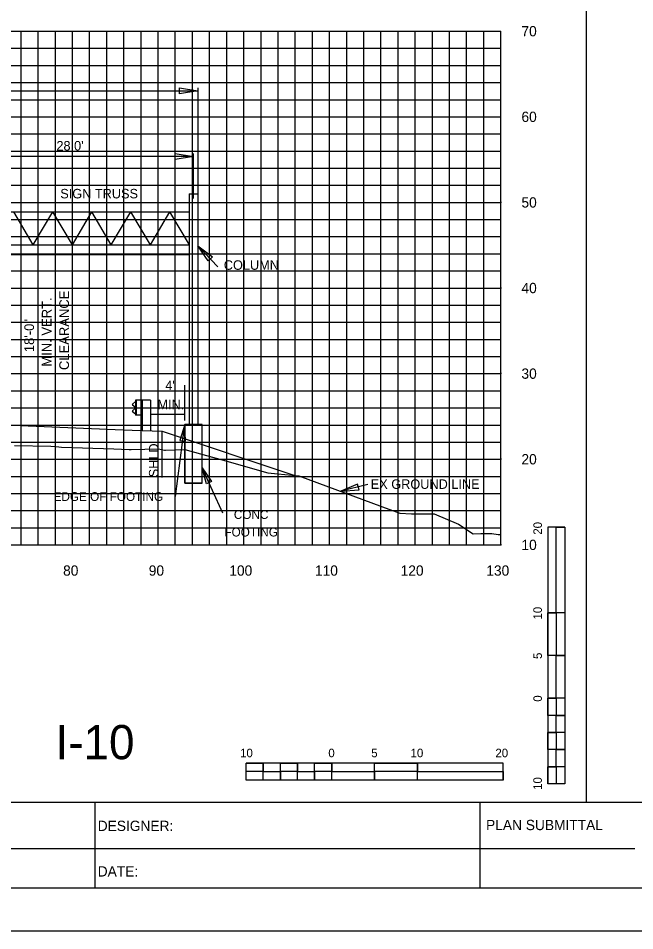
# Model space of a CAD drawing. Extents: x 2193008 to 2198143, y 1236112 to 1237864.
# Drawn here: x 2195658.4 to 2195730.3, y 1237118 to 1237224.6 of the extents above; entities that cross this region are included whole.
import ezdxf

# ---------------------------------------------------------------- set-up
doc = ezdxf.new("R2010")
doc.units = 0
for name, color, linetype in [('3', 7, 'Continuous'), ('31', 7, 'Continuous'), ('60', 7, 'Continuous'), ('ANNO-TXT', 7, 'Continuous'), ('Default', 7, 'Continuous'), ('GSDIMS', 7, 'Continuous'), ('Level 1', 7, 'Continuous'), ('Level 33', 7, 'Continuous'), ('Level 55', 7, 'Continuous'), ('Level 61', 7, 'Continuous'), ('LIMT-CSLINE', 7, 'Continuous'), ('M-ROADS', 7, 'Continuous'), ('SHT-BNDRY', 7, 'Continuous'), ('V7Level1', 7, 'Continuous')]:
    doc.layers.add(name, color=color, linetype=linetype)

msp = doc.modelspace()

# ---------------------------------------------------------------- linework, layer by layer
msp.add_lwpolyline([(2195574.71, 1237133.05), (2195874.71, 1237133.05), (2195874.71, 1237323.05), (2195574.71, 1237323.05)], close=True)
at = {"layer": '3'}
for p, q in [((2195724.71, 1237133.05), (2195724.71, 1237228.05)), ((2195724.71, 1237133.05), (2195724.71, 1237228.05)), ((2195679.32, 1237216.5), (2195679.32, 1237204.12)), ((2195584.25, 1237216.15), (2195679.32, 1237216.15)), ((2195678.32, 1237204.12), (2195678.32, 1237177.18)), ((2195679.32, 1237204.12), (2195679.32, 1237177.18)), ((2195681.69, 1237195.6), (2195679.32, 1237198.04)), ((2195677.82, 1237177.62), (2195677.82, 1237181.77)), ((2195676.73, 1237168.75), (2195677.82, 1237177.18)), ((2195679.84, 1237177.18), (2195677.82, 1237177.18)), ((2195677.82, 1237170.32), (2195677.82, 1237177.18)), ((2195679.84, 1237170.32), (2195679.84, 1237177.18)), ((2195682.27, 1237166.81), (2195679.84, 1237172.11)), ((2195679.84, 1237170.32), (2195677.82, 1237170.32)), ((2195699.19, 1237170.15), (2195696.04, 1237169.37))]:
    msp.add_line(p, q, dxfattribs=at)
at = {"layer": '60'}
for p, q in [((2195714.71, 1237163.11), (2195714.71, 1237223.11)), ((2195714.77, 1237203.11), (2195714.71, 1237203.11)), ((2195714.77, 1237193.11), (2195714.71, 1237193.11)), ((2195714.77, 1237183.11), (2195714.71, 1237183.11)), ((2195714.77, 1237173.11), (2195714.71, 1237173.11)), ((2195584.71, 1237163.11), (2195714.71, 1237163.11)), ((2195664.71, 1237163.05), (2195664.71, 1237163.11)), ((2195674.71, 1237163.05), (2195674.71, 1237163.11)), ((2195684.71, 1237163.05), (2195684.71, 1237163.11)), ((2195694.71, 1237163.05), (2195694.71, 1237163.11)), ((2195704.71, 1237163.05), (2195704.71, 1237163.11)), ((2195714.71, 1237163.05), (2195714.71, 1237163.11)), ((2195714.77, 1237163.11), (2195714.71, 1237163.11))]:
    msp.add_line(p, q, dxfattribs=at)
msp.add_lwpolyline([(2195587.2, 1237175.36), (2195596.63, 1237175.74), (2195608.63, 1237176), (2195619.96, 1237176.25), (2195631.96, 1237176.52), (2195643.96, 1237176.78), (2195657.69, 1237177.08), (2195669.69, 1237176.6), (2195671.69, 1237176.52), (2195675.19, 1237176.38), (2195690.66, 1237171.23)], dxfattribs=at)
at = {"layer": 'Default'}
msp.add_line((2195678.82, 1237203.57), (2195678.82, 1237208.83), dxfattribs=at)
at = {"layer": 'GSDIMS'}
for p, q in [((2195678.82, 1237208.48), (2195650.7, 1237208.48)), ((2195678.32, 1237204.12), (2195679.32, 1237204.12)), ((2195650.7, 1237203.12), (2195678.32, 1237203.12)), ((2195650.7, 1237202.01), (2195678.32, 1237202.01)), ((2195657.81, 1237202.01), (2195660.09, 1237198.15)), ((2195662.37, 1237202.01), (2195660.09, 1237198.15)), ((2195662.37, 1237202.01), (2195664.65, 1237198.15)), ((2195666.93, 1237202.01), (2195664.65, 1237198.15)), ((2195666.93, 1237202.01), (2195669.2, 1237198.15)), ((2195671.48, 1237202.01), (2195669.2, 1237198.15)), ((2195671.48, 1237202.01), (2195673.76, 1237198.15)), ((2195676.04, 1237202.01), (2195673.76, 1237198.15)), ((2195676.04, 1237202.01), (2195678.32, 1237198.15)), ((2195650.7, 1237198.15), (2195678.32, 1237198.15)), ((2195650.7, 1237197.04), (2195678.32, 1237197.04)), ((2195675.19, 1237170.97), (2195675.19, 1237176.38))]:
    msp.add_line(p, q, dxfattribs=at)
for points in [[(2195679.32, 1237216.15), (2195677.19, 1237215.81), (2195677.19, 1237216.5)], [(2195678.82, 1237208.48), (2195676.69, 1237208.13), (2195676.69, 1237208.83)], [(2195679.32, 1237198.04), (2195681.04, 1237196.77), (2195680.53, 1237196.29)], [(2195677.82, 1237177.18), (2195677.25, 1237175.31), (2195677.89, 1237175.23)], [(2195679.84, 1237172.11), (2195680.93, 1237170.5), (2195680.35, 1237170.23)], [(2195696.04, 1237169.37), (2195698.17, 1237169.53), (2195697.99, 1237170.21)]]:
    msp.add_lwpolyline(points, close=True, dxfattribs=at)
at = {"layer": 'Level 1'}
for p, q in [((2195672.07, 1237179.85), (2195671.71, 1237179.55)), ((2195671.71, 1237179.48), (2195672.07, 1237179.2)), ((2195672.07, 1237179.06), (2195671.71, 1237178.76)), ((2195672.07, 1237180), (2195672.07, 1237178.25)), ((2195673.82, 1237180), (2195672.07, 1237180)), ((2195672.12, 1237180), (2195672.12, 1237178.25)), ((2195672.77, 1237180), (2195672.77, 1237178.25)), ((2195672.82, 1237180), (2195672.82, 1237176.48)), ((2195673.82, 1237180), (2195673.82, 1237176.44)), ((2195671.71, 1237178.69), (2195672.07, 1237178.4)), ((2195672.82, 1237178.25), (2195672.07, 1237178.25)), ((2195720.18, 1237165.19), (2195720.18, 1237135.19)), ((2195722.18, 1237165.19), (2195720.18, 1237165.19)), ((2195722.18, 1237165.19), (2195722.18, 1237155.19)), ((2195722.18, 1237165.19), (2195722.18, 1237135.19)), ((2195721.18, 1237155.19), (2195720.18, 1237155.19)), ((2195722.18, 1237155.19), (2195720.18, 1237155.19)), ((2195721.18, 1237155.19), (2195721.18, 1237150.19)), ((2195722.18, 1237150.19), (2195720.18, 1237150.19)), ((2195722.18, 1237150.19), (2195721.18, 1237150.19)), ((2195722.18, 1237150.19), (2195722.18, 1237145.19)), ((2195721.18, 1237145.19), (2195720.18, 1237145.19)), ((2195722.18, 1237145.19), (2195720.18, 1237145.19)), ((2195721.18, 1237145.19), (2195721.18, 1237143.19)), ((2195722.18, 1237143.19), (2195721.18, 1237143.19)), ((2195722.18, 1237143.19), (2195722.18, 1237141.19)), ((2195721.18, 1237141.19), (2195720.18, 1237141.19)), ((2195721.18, 1237141.19), (2195721.18, 1237139.19)), ((2195722.18, 1237139.19), (2195721.18, 1237139.19)), ((2195722.18, 1237139.19), (2195722.18, 1237137.19)), ((2195714.97, 1237137.63), (2195684.97, 1237137.63)), ((2195684.97, 1237135.63), (2195684.97, 1237137.63)), ((2195686.97, 1237136.63), (2195686.97, 1237137.63)), ((2195690.97, 1237136.63), (2195690.97, 1237137.63)), ((2195694.97, 1237136.63), (2195694.97, 1237137.63)), ((2195694.97, 1237135.63), (2195694.97, 1237137.63)), ((2195699.97, 1237135.63), (2195699.97, 1237137.63)), ((2195704.97, 1237136.63), (2195704.97, 1237137.63)), ((2195704.97, 1237135.63), (2195704.97, 1237137.63)), ((2195714.97, 1237135.63), (2195714.97, 1237137.63)), ((2195686.97, 1237136.63), (2195684.97, 1237136.63)), ((2195688.97, 1237135.63), (2195688.97, 1237136.63)), ((2195690.97, 1237136.63), (2195688.97, 1237136.63)), ((2195692.97, 1237135.63), (2195692.97, 1237136.63)), ((2195694.97, 1237136.63), (2195692.97, 1237136.63)), ((2195699.97, 1237135.63), (2195699.97, 1237136.63)), ((2195704.97, 1237136.63), (2195699.97, 1237136.63)), ((2195721.18, 1237137.19), (2195720.18, 1237137.19)), ((2195721.18, 1237137.19), (2195721.18, 1237135.19)), ((2195714.97, 1237135.63), (2195684.97, 1237135.63)), ((2195688.97, 1237135.63), (2195686.97, 1237135.63)), ((2195692.97, 1237135.63), (2195690.97, 1237135.63)), ((2195699.97, 1237135.63), (2195694.97, 1237135.63)), ((2195714.97, 1237135.63), (2195704.97, 1237135.63)), ((2195722.18, 1237135.19), (2195720.18, 1237135.19))]:
    msp.add_line(p, q, dxfattribs=at)
for points in [[(2195721.18, 1237155.19), (2195721.18, 1237165.19), (2195722.18, 1237165.19), (2195722.18, 1237155.19)], [(2195720.18, 1237150.19), (2195720.18, 1237155.19), (2195721.18, 1237155.19), (2195721.18, 1237150.19)], [(2195721.18, 1237145.19), (2195721.18, 1237150.19), (2195722.18, 1237150.19), (2195722.18, 1237145.19)], [(2195720.18, 1237143.19), (2195720.18, 1237145.19), (2195721.18, 1237145.19), (2195721.18, 1237143.19)], [(2195721.18, 1237141.19), (2195721.18, 1237143.19), (2195722.18, 1237143.19), (2195722.18, 1237141.19)], [(2195720.18, 1237139.19), (2195720.18, 1237141.19), (2195721.18, 1237141.19), (2195721.18, 1237139.19)], [(2195721.18, 1237137.19), (2195721.18, 1237139.19), (2195722.18, 1237139.19), (2195722.18, 1237137.19)], [(2195684.97, 1237137.63), (2195686.97, 1237137.63), (2195686.97, 1237136.63), (2195684.97, 1237136.63)], [(2195688.97, 1237137.63), (2195690.97, 1237137.63), (2195690.97, 1237136.63), (2195688.97, 1237136.63)], [(2195692.97, 1237137.63), (2195694.97, 1237137.63), (2195694.97, 1237136.63), (2195692.97, 1237136.63)], [(2195699.97, 1237137.63), (2195704.97, 1237137.63), (2195704.97, 1237136.63), (2195699.97, 1237136.63)], [(2195686.97, 1237136.63), (2195688.97, 1237136.63), (2195688.97, 1237135.63), (2195686.97, 1237135.63)], [(2195690.97, 1237136.63), (2195692.97, 1237136.63), (2195692.97, 1237135.63), (2195690.97, 1237135.63)], [(2195694.97, 1237136.63), (2195699.97, 1237136.63), (2195699.97, 1237135.63), (2195694.97, 1237135.63)], [(2195704.97, 1237136.63), (2195714.97, 1237136.63), (2195714.97, 1237135.63), (2195704.97, 1237135.63)], [(2195720.18, 1237135.19), (2195720.18, 1237137.19), (2195721.18, 1237137.19), (2195721.18, 1237135.19)]]:
    msp.add_lwpolyline(points, close=True, dxfattribs=at)
for centre in [(2195671.74, 1237179.52), (2195671.74, 1237178.72)]:
    msp.add_arc(centre, 0.05, 135, 226.6208, dxfattribs=at)
at = {"layer": 'Level 61'}
msp.add_line((2195673.82, 1237178.37), (2195677.82, 1237178.37), dxfattribs=at)
at = {"layer": 'M-ROADS'}
for p, q in [((2195584.71, 1237223.11), (2195714.71, 1237223.11)), ((2195658.71, 1237163.11), (2195658.71, 1237223.11)), ((2195660.71, 1237163.11), (2195660.71, 1237223.11)), ((2195662.71, 1237163.11), (2195662.71, 1237223.11)), ((2195664.71, 1237163.11), (2195664.71, 1237223.11)), ((2195666.71, 1237163.11), (2195666.71, 1237223.11)), ((2195668.71, 1237163.11), (2195668.71, 1237223.11)), ((2195670.71, 1237163.11), (2195670.71, 1237223.11)), ((2195672.71, 1237163.11), (2195672.71, 1237223.11)), ((2195674.71, 1237163.11), (2195674.71, 1237223.11)), ((2195676.71, 1237163.11), (2195676.71, 1237223.11)), ((2195678.71, 1237163.11), (2195678.71, 1237223.11)), ((2195680.71, 1237163.11), (2195680.71, 1237223.11)), ((2195682.71, 1237163.11), (2195682.71, 1237223.11)), ((2195684.71, 1237163.11), (2195684.71, 1237223.11)), ((2195686.71, 1237163.11), (2195686.71, 1237223.11)), ((2195688.71, 1237163.11), (2195688.71, 1237223.11)), ((2195690.71, 1237163.11), (2195690.71, 1237223.11)), ((2195692.71, 1237163.11), (2195692.71, 1237223.11)), ((2195694.71, 1237163.11), (2195694.71, 1237223.11)), ((2195696.71, 1237163.11), (2195696.71, 1237223.11)), ((2195698.71, 1237163.11), (2195698.71, 1237223.11)), ((2195700.71, 1237163.11), (2195700.71, 1237223.11)), ((2195702.71, 1237163.11), (2195702.71, 1237223.11)), ((2195704.71, 1237163.11), (2195704.71, 1237223.11)), ((2195706.71, 1237163.11), (2195706.71, 1237223.11)), ((2195708.71, 1237163.11), (2195708.71, 1237223.11)), ((2195710.71, 1237163.11), (2195710.71, 1237223.11)), ((2195712.71, 1237163.11), (2195712.71, 1237223.11)), ((2195714.71, 1237163.11), (2195714.71, 1237223.11)), ((2195584.71, 1237221.11), (2195714.71, 1237221.11)), ((2195584.71, 1237219.11), (2195714.71, 1237219.11)), ((2195584.71, 1237217.11), (2195714.71, 1237217.11)), ((2195584.71, 1237215.11), (2195714.71, 1237215.11)), ((2195584.71, 1237213.11), (2195714.71, 1237213.11)), ((2195584.71, 1237211.11), (2195714.71, 1237211.11)), ((2195584.71, 1237209.11), (2195714.71, 1237209.11)), ((2195584.71, 1237207.11), (2195714.71, 1237207.11)), ((2195584.71, 1237205.11), (2195714.71, 1237205.11)), ((2195584.71, 1237203.11), (2195714.71, 1237203.11)), ((2195584.71, 1237201.11), (2195714.71, 1237201.11)), ((2195584.71, 1237199.11), (2195714.71, 1237199.11)), ((2195584.71, 1237197.11), (2195714.71, 1237197.11)), ((2195584.71, 1237195.11), (2195714.71, 1237195.11)), ((2195584.71, 1237193.11), (2195714.71, 1237193.11)), ((2195584.71, 1237191.11), (2195714.71, 1237191.11)), ((2195584.71, 1237189.11), (2195714.71, 1237189.11)), ((2195584.71, 1237187.11), (2195714.71, 1237187.11)), ((2195584.71, 1237185.11), (2195714.71, 1237185.11)), ((2195584.71, 1237183.11), (2195714.71, 1237183.11)), ((2195584.71, 1237181.11), (2195714.71, 1237181.11)), ((2195584.71, 1237179.11), (2195714.71, 1237179.11)), ((2195584.71, 1237177.11), (2195714.71, 1237177.11)), ((2195584.71, 1237175.11), (2195714.71, 1237175.11)), ((2195584.71, 1237173.11), (2195714.71, 1237173.11)), ((2195584.71, 1237171.11), (2195714.71, 1237171.11)), ((2195584.71, 1237169.11), (2195714.71, 1237169.11)), ((2195584.71, 1237167.11), (2195714.71, 1237167.11)), ((2195584.71, 1237165.11), (2195714.71, 1237165.11)), ((2195584.71, 1237163.11), (2195714.71, 1237163.11))]:
    msp.add_line(p, q, dxfattribs=at)
msp.add_lwpolyline([(2195549.71, 1237118.04), (2195889.71, 1237118.04), (2195889.71, 1237338.04), (2195549.71, 1237338.04)], close=True, dxfattribs=at)
msp.add_lwpolyline([(2195657.92, 1237174.73), (2195662.19, 1237174.62), (2195663.13, 1237174.55), (2195663.43, 1237174.53), (2195669.52, 1237174.31), (2195671.31, 1237174.26), (2195671.57, 1237174.26), (2195674.75, 1237174.31), (2195675.43, 1237174.18), (2195675.49, 1237174.18), (2195675.57, 1237174.18), (2195677.83, 1237174.26), (2195682.17, 1237173.06), (2195687.51, 1237171.54), (2195688.69, 1237171.42), (2195691.13, 1237171.18), (2195700.88, 1237167.57), (2195702.9, 1237166.83), (2195704.29, 1237166.73), (2195705.74, 1237166.73), (2195706.92, 1237166.73), (2195709.75, 1237165.54), (2195711.47, 1237164.39), (2195712.36, 1237164.44), (2195713.65, 1237164.44), (2195714.38, 1237164.33), (2195714.71, 1237164.34)], dxfattribs=at)
at = {"layer": 'SHT-BNDRY'}
for p, q in [((2195667.37, 1237123.04), (2195667.37, 1237133.05)), ((2195712.3, 1237123.04), (2195712.3, 1237133.05)), ((2195574.71, 1237127.65), (2195730.33, 1237127.65))]:
    msp.add_line(p, q, dxfattribs=at)
msp.add_lwpolyline([(2195562.21, 1237123.04), (2195884.71, 1237123.04), (2195884.71, 1237333.04), (2195562.21, 1237333.04)], close=True, dxfattribs=at)
at = {"layer": 'V7Level1'}
msp.add_lwpolyline([(2195677.82, 1237170.32), (2195679.84, 1237170.32), (2195679.84, 1237177.18), (2195677.82, 1237177.18)], close=True, dxfattribs=at)

# ---------------------------------------------------------------- texts
at = {"layer": '31'}
for s, p in [('70', (2195717.11, 1237222.51)), ('60', (2195717.11, 1237212.51)), ('50', (2195717.11, 1237202.51)), ('40', (2195717.11, 1237192.51)), ('30', (2195717.11, 1237182.51)), ('20', (2195717.11, 1237172.51)), ('10', (2195717.11, 1237162.51))]:
    msp.add_text(s, height=1.2, dxfattribs=at).set_placement(p)
at = {"layer": 'ANNO-TXT'}
for s, p in [('PLAN SUBMITTAL', (2195712.98, 1237129.79)), ('DESIGNER:', (2195667.65, 1237129.69)), ('DATE:', (2195667.65, 1237124.37))]:
    msp.add_text(s, height=1.2, rotation=360, dxfattribs=at).set_placement(p)
at = {"layer": 'Level 1'}
for s, height, rotation, p in [('20', 0.999, 90.0572, (2195719.5, 1237164.3)), ('10', 0.999, 90.0572, (2195719.5, 1237154.39)), ('5', 1, 90.0572, (2195719.5, 1237149.78)), ('0', 1, 90.0572, (2195719.5, 1237144.79)), ('10', 0.999, 0.0572, (2195684.27, 1237138.3)), ('0', 1, 0.0572, (2195694.57, 1237138.3)), ('5', 0.999, 0.0572, (2195699.58, 1237138.3)), ('10', 0.999, 0.0572, (2195704.17, 1237138.3)), ('20', 0.999, 0.0572, (2195714.07, 1237138.3)), ('10', 0.999, 90.0572, (2195719.5, 1237134.49))]:
    msp.add_text(s, height=height, rotation=rotation, dxfattribs=at).set_placement(p)
at = {"layer": 'Level 33'}
msp.add_text('I-10', height=3.998, rotation=360, dxfattribs=at).set_placement((2195662.73, 1237138.07))
at = {"layer": 'Level 55'}
for s, height, p in [("28.0'", 1.11, (2195662.83, 1237209.17)), ('SIGN TRUSS', 1.11, (2195663.28, 1237203.58)), ('COLUMN', 1.11, (2195682.37, 1237195.24)), ("4'", 1.11, (2195675.54, 1237181.18)), ('MIN.', 1.11, (2195674.62, 1237178.96)), ('EX GROUND LINE', 1.1105, (2195699.52, 1237169.65)), ('EDGE OF FOOTING', 1.0246, (2195662.5, 1237168.24)), ('CONC', 1.025, (2195683.54, 1237166.14)), ('FOOTING', 1.025, (2195682.44, 1237164.09))]:
    msp.add_text(s, height=height, dxfattribs=at).set_placement(p)
for s, height, p in [('MIN. VERT.', 1.135, (2195662.26, 1237183.93)), ('CLEARANCE', 1.135, (2195664.3, 1237183.53)), ('18\'-0"', 1.135, (2195660.22, 1237185.62)), ('SHLD', 1.11, (2195674.74, 1237171))]:
    msp.add_text(s, height=height, rotation=90, dxfattribs=at).set_placement(p)
at = {"layer": 'LIMT-CSLINE'}
for s, p in [('80', (2195663.61, 1237159.51)), ('90', (2195673.61, 1237159.51)), ('100', (2195683.01, 1237159.51)), ('110', (2195693.01, 1237159.51)), ('120', (2195703.01, 1237159.51)), ('130', (2195713.01, 1237159.51))]:
    msp.add_text(s, height=1.2, dxfattribs=at).set_placement(p)

doc.saveas('drawing.dxf')
